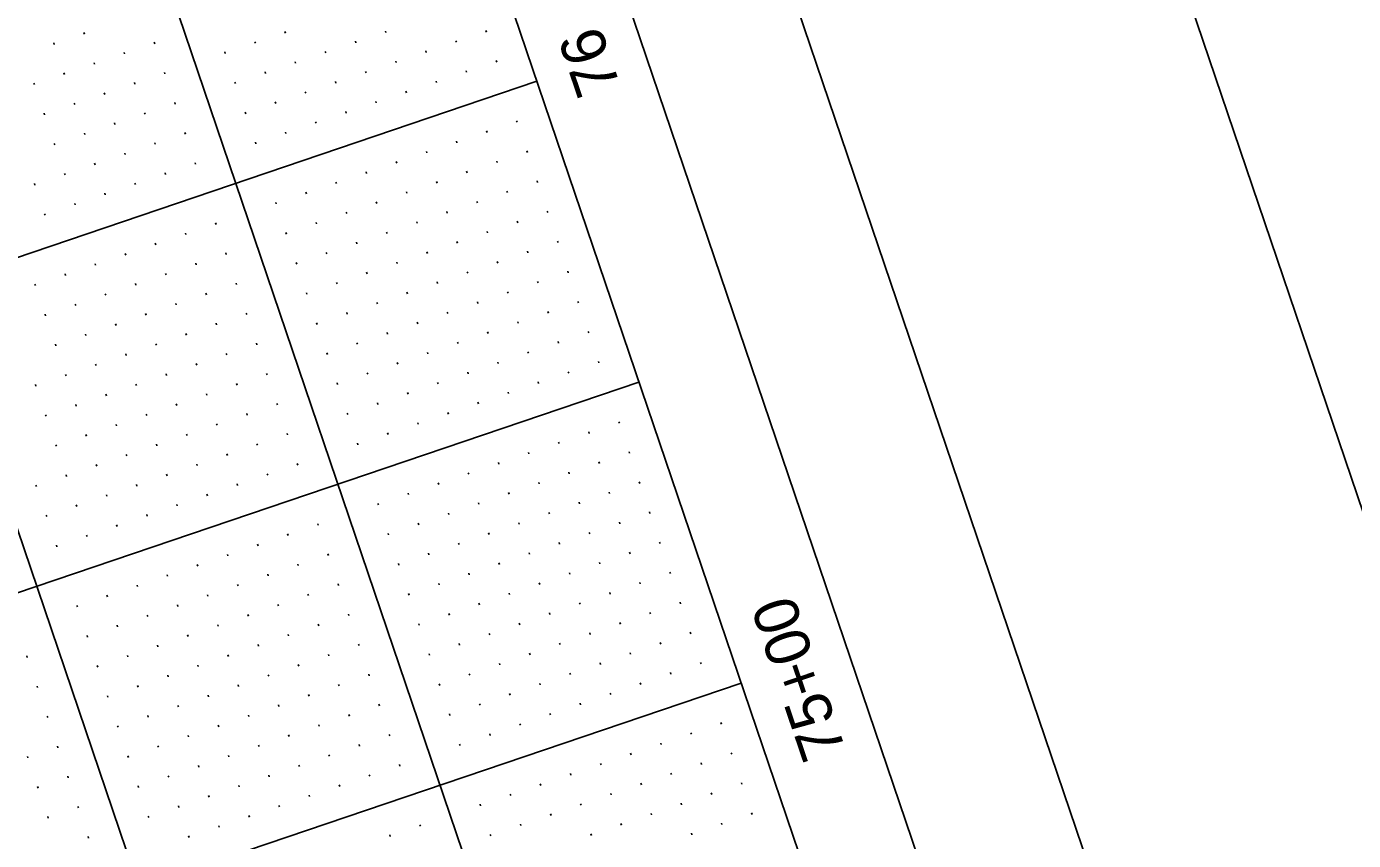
# Model space of a CAD drawing. Extents: x 2150800 to 2152547, y 141860 to 143950.
# Drawn here: x 2152172.8 to 2152381.5, y 142583.1 to 142711.2 of the extents above; entities that cross this region are included whole.
import ezdxf

# ---------------------------------------------------------------- set-up
doc = ezdxf.new("R2010")
doc.units = 0
for name, color, linetype in [('SHT_Plan_Profile_Sheet_Sta_Txt', 7, 'Continuous'), ('SHT_Plot_Shape_Full', 7, 'Continuous'), ('SHT_Plot_Shape_Half', 7, 'Continuous'), ('SHT_Profile_Grid_Major', 7, 'Continuous'), ('SHT_Profile_Grid_Minor', 7, 'Continuous'), ('SHT_Sheet_Border', 7, 'Continuous')]:
    doc.layers.add(name, color=color, linetype=linetype)

msp = doc.modelspace()

# ---------------------------------------------------------------- linework, layer by layer
at = {"layer": 'SHT_Plot_Shape_Full'}
msp.add_lwpolyline([(2151378.63, 141860.13), (2150800.36, 143564.71), (2151936.74, 143950.23), (2152515.02, 142245.65)], close=True, dxfattribs=at)
at = {"layer": 'SHT_Plot_Shape_Half'}
msp.add_lwpolyline([(2151391.39, 141950.92), (2150845.24, 143560.8), (2151886.93, 143914.19), (2152433.08, 142304.31)], close=True, dxfattribs=at)
at = {"layer": 'SHT_Profile_Grid_Major'}
for p, q in [((2152314.16, 142366.92), (2151808.17, 143858.43)), ((2152266.81, 142350.86), (2151760.82, 143842.37)), ((2152253.08, 142702.59), (2151779.81, 142542.04)), ((2152269.15, 142655.25), (2151840.6, 142509.86)), ((2152285.21, 142607.9), (2151835.31, 142455.27))]:
    msp.add_line(p, q, dxfattribs=at)
at = {"layer": 'SHT_Profile_Grid_Minor'}
for p, q in [((2152177.2, 142708.4), (2152177.11, 142708.63)), ((2152181.93, 142710), (2152181.85, 142710.24)), ((2152193.01, 142708.48), (2152192.93, 142708.72)), ((2152208.82, 142708.57), (2152208.74, 142708.8)), ((2152213.55, 142710.17), (2152213.47, 142710.41)), ((2152224.63, 142708.65), (2152224.55, 142708.89)), ((2152229.36, 142710.26), (2152229.28, 142710.49)), ((2152240.44, 142708.73), (2152240.36, 142708.97)), ((2152245.17, 142710.34), (2152245.09, 142710.58)), ((2152188.27, 142706.88), (2152188.19, 142707.11)), ((2152204.08, 142706.96), (2152204, 142707.2)), ((2152219.89, 142707.04), (2152219.81, 142707.28)), ((2152235.7, 142707.13), (2152235.62, 142707.36)), ((2152183.54, 142705.27), (2152183.46, 142705.51)), ((2152215.16, 142705.44), (2152215.08, 142705.67)), ((2152230.97, 142705.52), (2152230.89, 142705.76)), ((2152246.78, 142705.6), (2152246.7, 142705.84)), ((2152178.8, 142703.66), (2152178.72, 142703.9)), ((2152189.88, 142702.14), (2152189.8, 142702.38)), ((2152194.61, 142703.75), (2152194.53, 142703.98)), ((2152205.69, 142702.22), (2152205.61, 142702.46)), ((2152210.42, 142703.83), (2152210.34, 142704.07)), ((2152221.5, 142702.31), (2152221.42, 142702.54)), ((2152226.23, 142703.91), (2152226.15, 142704.15)), ((2152237.31, 142702.39), (2152237.23, 142702.63)), ((2152242.05, 142704), (2152241.97, 142704.24)), ((2152174.07, 142702.06), (2152173.99, 142702.29)), ((2152185.14, 142700.53), (2152185.06, 142700.77)), ((2152216.77, 142700.7), (2152216.68, 142700.94)), ((2152232.58, 142700.79), (2152232.5, 142701.02)), ((2152180.41, 142698.93), (2152180.33, 142699.16)), ((2152196.22, 142699.01), (2152196.14, 142699.25)), ((2152212.03, 142699.1), (2152211.95, 142699.33)), ((2152227.84, 142699.18), (2152227.76, 142699.42)), ((2152175.67, 142697.32), (2152175.59, 142697.56)), ((2152191.48, 142697.41), (2152191.4, 142697.64)), ((2152207.3, 142697.49), (2152207.21, 142697.73)), ((2152218.37, 142695.97), (2152218.29, 142696.2)), ((2152223.11, 142697.57), (2152223.03, 142697.81)), ((2152249.99, 142696.13), (2152249.91, 142696.37)), ((2152182.01, 142694.19), (2152181.93, 142694.43)), ((2152186.75, 142695.8), (2152186.67, 142696.04)), ((2152197.83, 142694.28), (2152197.74, 142694.51)), ((2152213.64, 142694.36), (2152213.56, 142694.6)), ((2152245.26, 142694.53), (2152245.18, 142694.77)), ((2152177.28, 142692.59), (2152177.2, 142692.82)), ((2152193.09, 142692.67), (2152193.01, 142692.91)), ((2152208.9, 142692.75), (2152208.82, 142692.99)), ((2152240.52, 142692.92), (2152240.44, 142693.16)), ((2152188.36, 142691.06), (2152188.28, 142691.3)), ((2152231.05, 142689.71), (2152230.97, 142689.95)), ((2152235.79, 142691.32), (2152235.71, 142691.55)), ((2152246.87, 142689.79), (2152246.78, 142690.03)), ((2152251.6, 142691.4), (2152251.52, 142691.64)), ((2152178.89, 142687.85), (2152178.81, 142688.09)), ((2152183.62, 142689.46), (2152183.54, 142689.69)), ((2152194.7, 142687.94), (2152194.62, 142688.17)), ((2152199.43, 142689.54), (2152199.35, 142689.78)), ((2152226.32, 142688.1), (2152226.24, 142688.34)), ((2152242.13, 142688.19), (2152242.05, 142688.42)), ((2152174.15, 142686.25), (2152174.07, 142686.48)), ((2152189.96, 142686.33), (2152189.88, 142686.57)), ((2152221.58, 142686.5), (2152221.5, 142686.73)), ((2152237.4, 142686.58), (2152237.31, 142686.82)), ((2152253.21, 142686.67), (2152253.13, 142686.9)), ((2152185.23, 142684.72), (2152185.15, 142684.96)), ((2152212.11, 142683.28), (2152212.03, 142683.52)), ((2152216.85, 142684.89), (2152216.77, 142685.13)), ((2152227.93, 142683.37), (2152227.84, 142683.61)), ((2152232.66, 142684.97), (2152232.58, 142685.21)), ((2152243.74, 142683.45), (2152243.66, 142683.69)), ((2152248.47, 142685.06), (2152248.39, 142685.3)), ((2152175.76, 142681.51), (2152175.68, 142681.75)), ((2152180.49, 142683.12), (2152180.41, 142683.35)), ((2152223.19, 142681.76), (2152223.11, 142682)), ((2152239, 142681.85), (2152238.92, 142682.08)), ((2152254.81, 142681.93), (2152254.73, 142682.17)), ((2152202.64, 142680.07), (2152202.56, 142680.31)), ((2152218.46, 142680.16), (2152218.38, 142680.39)), ((2152234.27, 142680.24), (2152234.19, 142680.48)), ((2152250.08, 142680.32), (2152250, 142680.56)), ((2152197.91, 142678.47), (2152197.83, 142678.7)), ((2152213.72, 142678.55), (2152213.64, 142678.79)), ((2152224.8, 142677.03), (2152224.72, 142677.26)), ((2152229.53, 142678.63), (2152229.45, 142678.87)), ((2152240.61, 142677.11), (2152240.53, 142677.35)), ((2152245.34, 142678.72), (2152245.26, 142678.95)), ((2152256.42, 142677.2), (2152256.34, 142677.43)), ((2152188.44, 142675.25), (2152188.36, 142675.49)), ((2152193.17, 142676.86), (2152193.09, 142677.1)), ((2152204.25, 142675.34), (2152204.17, 142675.57)), ((2152220.06, 142675.42), (2152219.98, 142675.66)), ((2152235.87, 142675.5), (2152235.79, 142675.74)), ((2152251.68, 142675.59), (2152251.6, 142675.83)), ((2152183.7, 142673.65), (2152183.62, 142673.88)), ((2152199.52, 142673.73), (2152199.44, 142673.97)), ((2152215.33, 142673.81), (2152215.25, 142674.05)), ((2152231.14, 142673.9), (2152231.06, 142674.14)), ((2152246.95, 142673.98), (2152246.87, 142674.22)), ((2152178.97, 142672.04), (2152178.89, 142672.28)), ((2152194.78, 142672.12), (2152194.7, 142672.36)), ((2152226.4, 142672.29), (2152226.32, 142672.53)), ((2152237.48, 142670.77), (2152237.4, 142671.01)), ((2152242.21, 142672.38), (2152242.13, 142672.61)), ((2152253.29, 142670.85), (2152253.21, 142671.09)), ((2152258.03, 142672.46), (2152257.94, 142672.7)), ((2152174.23, 142670.43), (2152174.15, 142670.67)), ((2152185.31, 142668.91), (2152185.23, 142669.15)), ((2152190.05, 142670.52), (2152189.97, 142670.75)), ((2152201.12, 142669), (2152201.04, 142669.23)), ((2152205.86, 142670.6), (2152205.78, 142670.84)), ((2152216.93, 142669.08), (2152216.85, 142669.32)), ((2152221.67, 142670.69), (2152221.59, 142670.92)), ((2152232.74, 142669.16), (2152232.66, 142669.4)), ((2152248.56, 142669.25), (2152248.48, 142669.48)), ((2152180.58, 142667.31), (2152180.5, 142667.54)), ((2152196.39, 142667.39), (2152196.31, 142667.63)), ((2152228.01, 142667.56), (2152227.93, 142667.79)), ((2152243.82, 142667.64), (2152243.74, 142667.88)), ((2152259.63, 142667.73), (2152259.55, 142667.96)), ((2152175.84, 142665.7), (2152175.76, 142665.94)), ((2152191.65, 142665.78), (2152191.57, 142666.02)), ((2152207.46, 142665.87), (2152207.38, 142666.1)), ((2152223.27, 142665.95), (2152223.19, 142666.19)), ((2152239.09, 142666.03), (2152239.01, 142666.27)), ((2152250.16, 142664.51), (2152250.08, 142664.75)), ((2152254.9, 142666.12), (2152254.82, 142666.36)), ((2152182.18, 142662.57), (2152182.1, 142662.81)), ((2152186.92, 142664.18), (2152186.84, 142664.41)), ((2152197.99, 142662.65), (2152197.91, 142662.89)), ((2152202.73, 142664.26), (2152202.65, 142664.5)), ((2152218.54, 142664.34), (2152218.46, 142664.58)), ((2152229.62, 142662.82), (2152229.54, 142663.06)), ((2152234.35, 142664.43), (2152234.27, 142664.67)), ((2152245.43, 142662.91), (2152245.35, 142663.14)), ((2152261.24, 142662.99), (2152261.16, 142663.23)), ((2152177.45, 142660.96), (2152177.37, 142661.2)), ((2152193.26, 142661.05), (2152193.18, 142661.28)), ((2152209.07, 142661.13), (2152208.99, 142661.37)), ((2152224.88, 142661.22), (2152224.8, 142661.45)), ((2152240.69, 142661.3), (2152240.61, 142661.54)), ((2152256.5, 142661.38), (2152256.42, 142661.62)), ((2152188.52, 142659.44), (2152188.44, 142659.68)), ((2152204.33, 142659.53), (2152204.25, 142659.76)), ((2152220.15, 142659.61), (2152220.07, 142659.85)), ((2152235.96, 142659.69), (2152235.88, 142659.93)), ((2152251.77, 142659.78), (2152251.69, 142660.01)), ((2152262.84, 142658.26), (2152262.76, 142658.49)), ((2152179.05, 142656.23), (2152178.97, 142656.47)), ((2152183.79, 142657.84), (2152183.71, 142658.07)), ((2152194.86, 142656.31), (2152194.78, 142656.55)), ((2152199.6, 142657.92), (2152199.52, 142658.16)), ((2152210.68, 142656.4), (2152210.6, 142656.63)), ((2152226.49, 142656.48), (2152226.41, 142656.72)), ((2152231.22, 142658.09), (2152231.14, 142658.32)), ((2152242.3, 142656.57), (2152242.22, 142656.8)), ((2152247.03, 142658.17), (2152246.95, 142658.41)), ((2152258.11, 142656.65), (2152258.03, 142656.89)), ((2152174.32, 142654.62), (2152174.24, 142654.86)), ((2152190.13, 142654.71), (2152190.05, 142654.94)), ((2152205.94, 142654.79), (2152205.86, 142655.03)), ((2152221.75, 142654.87), (2152221.67, 142655.11)), ((2152237.56, 142654.96), (2152237.48, 142655.2)), ((2152253.37, 142655.04), (2152253.29, 142655.28)), ((2152185.39, 142653.1), (2152185.31, 142653.34)), ((2152201.21, 142653.18), (2152201.13, 142653.42)), ((2152232.83, 142653.35), (2152232.75, 142653.59)), ((2152248.64, 142653.44), (2152248.56, 142653.67)), ((2152180.66, 142651.49), (2152180.58, 142651.73)), ((2152191.74, 142649.97), (2152191.66, 142650.21)), ((2152196.47, 142651.58), (2152196.39, 142651.81)), ((2152207.55, 142650.06), (2152207.47, 142650.29)), ((2152212.28, 142651.66), (2152212.2, 142651.9)), ((2152223.36, 142650.14), (2152223.28, 142650.38)), ((2152228.09, 142651.75), (2152228.01, 142651.98)), ((2152239.17, 142650.22), (2152239.09, 142650.46)), ((2152243.9, 142651.83), (2152243.82, 142652.07)), ((2152175.92, 142649.89), (2152175.84, 142650.12)), ((2152187, 142648.37), (2152186.92, 142648.6)), ((2152202.81, 142648.45), (2152202.73, 142648.69)), ((2152234.43, 142648.62), (2152234.35, 142648.85)), ((2152266.06, 142648.79), (2152265.98, 142649.02)), ((2152182.27, 142646.76), (2152182.19, 142647)), ((2152198.08, 142646.84), (2152198, 142647.08)), ((2152213.89, 142646.93), (2152213.81, 142647.16)), ((2152229.7, 142647.01), (2152229.62, 142647.25)), ((2152261.32, 142647.18), (2152261.24, 142647.42)), ((2152177.53, 142645.15), (2152177.45, 142645.39)), ((2152193.34, 142645.24), (2152193.26, 142645.47)), ((2152204.42, 142643.71), (2152204.34, 142643.95)), ((2152209.15, 142645.32), (2152209.07, 142645.56)), ((2152224.96, 142645.4), (2152224.88, 142645.64)), ((2152251.85, 142643.97), (2152251.77, 142644.2)), ((2152256.59, 142645.57), (2152256.51, 142645.81)), ((2152267.66, 142644.05), (2152267.58, 142644.29)), ((2152183.87, 142642.02), (2152183.79, 142642.26)), ((2152188.61, 142643.63), (2152188.53, 142643.87)), ((2152199.68, 142642.11), (2152199.6, 142642.34)), ((2152215.49, 142642.19), (2152215.41, 142642.43)), ((2152247.12, 142642.36), (2152247.04, 142642.6)), ((2152262.93, 142642.44), (2152262.85, 142642.68)), ((2152179.14, 142640.42), (2152179.06, 142640.65)), ((2152194.95, 142640.5), (2152194.87, 142640.74)), ((2152210.76, 142640.59), (2152210.68, 142640.82)), ((2152242.38, 142640.75), (2152242.3, 142640.99)), ((2152258.19, 142640.84), (2152258.11, 142641.07)), ((2152174.4, 142638.81), (2152174.32, 142639.05)), ((2152190.21, 142638.9), (2152190.13, 142639.13)), ((2152206.02, 142638.98), (2152205.94, 142639.22)), ((2152232.91, 142637.54), (2152232.83, 142637.78)), ((2152237.65, 142639.15), (2152237.57, 142639.38)), ((2152248.72, 142637.63), (2152248.64, 142637.86)), ((2152253.46, 142639.23), (2152253.38, 142639.47)), ((2152264.53, 142637.71), (2152264.45, 142637.95)), ((2152269.27, 142639.32), (2152269.19, 142639.55)), ((2152180.74, 142635.68), (2152180.66, 142635.92)), ((2152185.48, 142637.29), (2152185.4, 142637.53)), ((2152196.55, 142635.77), (2152196.47, 142636)), ((2152201.29, 142637.37), (2152201.21, 142637.61)), ((2152228.18, 142635.93), (2152228.1, 142636.17)), ((2152243.99, 142636.02), (2152243.91, 142636.26)), ((2152259.8, 142636.1), (2152259.72, 142636.34)), ((2152176.01, 142634.08), (2152175.93, 142634.31)), ((2152191.82, 142634.16), (2152191.74, 142634.4)), ((2152239.25, 142634.41), (2152239.17, 142634.65)), ((2152255.06, 142634.5), (2152254.98, 142634.73)), ((2152270.88, 142634.58), (2152270.8, 142634.82)), ((2152187.09, 142632.55), (2152187, 142632.79)), ((2152218.71, 142632.72), (2152218.63, 142632.96)), ((2152229.78, 142631.2), (2152229.7, 142631.44)), ((2152234.52, 142632.81), (2152234.44, 142633.04)), ((2152245.59, 142631.28), (2152245.51, 142631.52)), ((2152250.33, 142632.89), (2152250.25, 142633.13)), ((2152261.41, 142631.37), (2152261.33, 142631.6)), ((2152266.14, 142632.97), (2152266.06, 142633.21)), ((2152177.62, 142629.34), (2152177.53, 142629.58)), ((2152182.35, 142630.95), (2152182.27, 142631.18)), ((2152209.24, 142629.51), (2152209.16, 142629.75)), ((2152213.97, 142631.12), (2152213.89, 142631.35)), ((2152240.86, 142629.68), (2152240.78, 142629.91)), ((2152256.67, 142629.76), (2152256.59, 142630)), ((2152272.48, 142629.85), (2152272.4, 142630.08)), ((2152204.5, 142627.9), (2152204.42, 142628.14)), ((2152220.31, 142627.99), (2152220.23, 142628.22)), ((2152236.12, 142628.07), (2152236.04, 142628.31)), ((2152251.94, 142628.16), (2152251.86, 142628.39)), ((2152267.75, 142628.24), (2152267.67, 142628.48)), ((2152199.77, 142626.3), (2152199.69, 142626.53)), ((2152215.58, 142626.38), (2152215.5, 142626.62)), ((2152231.39, 142626.47), (2152231.31, 142626.7)), ((2152242.47, 142624.94), (2152242.39, 142625.18)), ((2152247.2, 142626.55), (2152247.12, 142626.79)), ((2152258.28, 142625.03), (2152258.2, 142625.26)), ((2152263.01, 142626.63), (2152262.93, 142626.87)), ((2152274.09, 142625.11), (2152274.01, 142625.35)), ((2152190.3, 142623.08), (2152190.22, 142623.32)), ((2152195.03, 142624.69), (2152194.95, 142624.93)), ((2152206.11, 142623.17), (2152206.03, 142623.41)), ((2152210.84, 142624.77), (2152210.76, 142625.01)), ((2152221.92, 142623.25), (2152221.84, 142623.49)), ((2152237.73, 142623.34), (2152237.65, 142623.57)), ((2152253.54, 142623.42), (2152253.46, 142623.66)), ((2152269.35, 142623.5), (2152269.27, 142623.74)), ((2152185.56, 142621.48), (2152185.48, 142621.71)), ((2152201.37, 142621.56), (2152201.29, 142621.8)), ((2152217.19, 142621.65), (2152217.1, 142621.88)), ((2152233, 142621.73), (2152232.92, 142621.97)), ((2152248.81, 142621.81), (2152248.73, 142622.05)), ((2152264.62, 142621.9), (2152264.54, 142622.13)), ((2152180.83, 142619.87), (2152180.75, 142620.11)), ((2152196.64, 142619.96), (2152196.56, 142620.19)), ((2152212.45, 142620.04), (2152212.37, 142620.28)), ((2152239.34, 142618.6), (2152239.26, 142618.84)), ((2152244.07, 142620.21), (2152243.99, 142620.44)), ((2152255.15, 142618.69), (2152255.07, 142618.92)), ((2152259.88, 142620.29), (2152259.8, 142620.53)), ((2152270.96, 142618.77), (2152270.88, 142619.01)), ((2152275.69, 142620.38), (2152275.61, 142620.61)), ((2152187.17, 142616.74), (2152187.09, 142616.98)), ((2152191.9, 142618.35), (2152191.82, 142618.59)), ((2152202.98, 142616.83), (2152202.9, 142617.06)), ((2152207.72, 142618.43), (2152207.63, 142618.67)), ((2152218.79, 142616.91), (2152218.71, 142617.15)), ((2152223.53, 142618.52), (2152223.45, 142618.75)), ((2152234.6, 142617), (2152234.52, 142617.23)), ((2152250.41, 142617.08), (2152250.33, 142617.32)), ((2152266.22, 142617.16), (2152266.14, 142617.4)), ((2152182.43, 142615.14), (2152182.35, 142615.37)), ((2152198.25, 142615.22), (2152198.16, 142615.46)), ((2152214.06, 142615.3), (2152213.98, 142615.54)), ((2152245.68, 142615.47), (2152245.6, 142615.71)), ((2152261.49, 142615.56), (2152261.41, 142615.79)), ((2152277.3, 142615.64), (2152277.22, 142615.88)), ((2152193.51, 142613.61), (2152193.43, 142613.85)), ((2152209.32, 142613.7), (2152209.24, 142613.94)), ((2152225.13, 142613.78), (2152225.05, 142614.02)), ((2152240.94, 142613.87), (2152240.86, 142614.1)), ((2152252.02, 142612.34), (2152251.94, 142612.58)), ((2152256.75, 142613.95), (2152256.67, 142614.19)), ((2152267.83, 142612.43), (2152267.75, 142612.66)), ((2152272.57, 142614.03), (2152272.49, 142614.27)), ((2152172.96, 142611.92), (2152172.88, 142612.16)), ((2152184.04, 142610.4), (2152183.96, 142610.64)), ((2152188.78, 142612.01), (2152188.7, 142612.24)), ((2152199.85, 142610.49), (2152199.77, 142610.72)), ((2152204.59, 142612.09), (2152204.51, 142612.33)), ((2152215.66, 142610.57), (2152215.58, 142610.81)), ((2152220.4, 142612.18), (2152220.32, 142612.41)), ((2152236.21, 142612.26), (2152236.13, 142612.5)), ((2152247.29, 142610.74), (2152247.2, 142610.97)), ((2152263.1, 142610.82), (2152263.02, 142611.06)), ((2152278.91, 142610.91), (2152278.83, 142611.14)), ((2152195.12, 142608.88), (2152195.04, 142609.12)), ((2152210.93, 142608.96), (2152210.85, 142609.2)), ((2152226.74, 142609.05), (2152226.66, 142609.28)), ((2152242.55, 142609.13), (2152242.47, 142609.37)), ((2152258.36, 142609.22), (2152258.28, 142609.45)), ((2152274.17, 142609.3), (2152274.09, 142609.54)), ((2152174.57, 142607.19), (2152174.49, 142607.43)), ((2152190.38, 142607.27), (2152190.3, 142607.51)), ((2152206.19, 142607.36), (2152206.11, 142607.59)), ((2152222, 142607.44), (2152221.92, 142607.68)), ((2152237.82, 142607.53), (2152237.73, 142607.76)), ((2152253.63, 142607.61), (2152253.55, 142607.85)), ((2152264.7, 142606.09), (2152264.62, 142606.32)), ((2152269.44, 142607.69), (2152269.36, 142607.93)), ((2152185.65, 142605.67), (2152185.57, 142605.9)), ((2152196.72, 142604.14), (2152196.64, 142604.38)), ((2152201.46, 142605.75), (2152201.38, 142605.99)), ((2152212.53, 142604.23), (2152212.45, 142604.47)), ((2152217.27, 142605.83), (2152217.19, 142606.07)), ((2152228.35, 142604.31), (2152228.26, 142604.55)), ((2152244.16, 142604.4), (2152244.08, 142604.63)), ((2152248.89, 142606), (2152248.81, 142606.24)), ((2152259.97, 142604.48), (2152259.89, 142604.72)), ((2152176.18, 142602.45), (2152176.1, 142602.69)), ((2152191.99, 142602.54), (2152191.91, 142602.78)), ((2152207.8, 142602.62), (2152207.72, 142602.86)), ((2152223.61, 142602.71), (2152223.53, 142602.94)), ((2152239.42, 142602.79), (2152239.34, 142603.03)), ((2152255.23, 142602.87), (2152255.15, 142603.11)), ((2152187.25, 142600.93), (2152187.17, 142601.17)), ((2152203.06, 142601.02), (2152202.98, 142601.25)), ((2152218.88, 142601.1), (2152218.8, 142601.34)), ((2152250.5, 142601.27), (2152250.42, 142601.5)), ((2152277.39, 142599.83), (2152277.3, 142600.07)), ((2152282.12, 142601.44), (2152282.04, 142601.67)), ((2152193.59, 142597.8), (2152193.51, 142598.04)), ((2152198.33, 142599.41), (2152198.25, 142599.65)), ((2152209.41, 142597.89), (2152209.33, 142598.12)), ((2152214.14, 142599.49), (2152214.06, 142599.73)), ((2152225.22, 142597.97), (2152225.14, 142598.21)), ((2152229.95, 142599.58), (2152229.87, 142599.81)), ((2152241.03, 142598.06), (2152240.95, 142598.29)), ((2152245.76, 142599.66), (2152245.68, 142599.9)), ((2152272.65, 142598.22), (2152272.57, 142598.46)), ((2152173.05, 142596.11), (2152172.97, 142596.35)), ((2152177.78, 142597.72), (2152177.7, 142597.96)), ((2152188.86, 142596.2), (2152188.78, 142596.43)), ((2152204.67, 142596.28), (2152204.59, 142596.52)), ((2152220.48, 142596.37), (2152220.4, 142596.6)), ((2152267.92, 142596.62), (2152267.83, 142596.85)), ((2152283.73, 142596.7), (2152283.65, 142596.94)), ((2152199.94, 142594.67), (2152199.86, 142594.91)), ((2152215.75, 142594.76), (2152215.67, 142595)), ((2152231.56, 142594.84), (2152231.48, 142595.08)), ((2152263.18, 142595.01), (2152263.1, 142595.25)), ((2152278.99, 142595.09), (2152278.91, 142595.33)), ((2152179.39, 142592.98), (2152179.31, 142593.22)), ((2152195.2, 142593.07), (2152195.12, 142593.31)), ((2152206.28, 142591.55), (2152206.2, 142591.78)), ((2152211.01, 142593.15), (2152210.93, 142593.39)), ((2152222.09, 142591.63), (2152222.01, 142591.87)), ((2152226.82, 142593.24), (2152226.74, 142593.47)), ((2152253.71, 142591.8), (2152253.63, 142592.03)), ((2152258.45, 142593.4), (2152258.37, 142593.64)), ((2152269.52, 142591.88), (2152269.44, 142592.12)), ((2152274.26, 142593.49), (2152274.18, 142593.73)), ((2152285.33, 142591.97), (2152285.25, 142592.2)), ((2152174.65, 142591.38), (2152174.57, 142591.61)), ((2152190.47, 142591.46), (2152190.39, 142591.7)), ((2152201.54, 142589.94), (2152201.46, 142590.18)), ((2152217.35, 142590.02), (2152217.27, 142590.26)), ((2152248.98, 142590.19), (2152248.9, 142590.43)), ((2152264.79, 142590.28), (2152264.71, 142590.51)), ((2152280.6, 142590.36), (2152280.52, 142590.6)), ((2152181, 142588.25), (2152180.92, 142588.49)), ((2152196.81, 142588.33), (2152196.73, 142588.57)), ((2152212.62, 142588.42), (2152212.54, 142588.65)), ((2152244.24, 142588.59), (2152244.16, 142588.82)), ((2152260.05, 142588.67), (2152259.97, 142588.91)), ((2152275.86, 142588.75), (2152275.78, 142588.99)), ((2152176.26, 142586.64), (2152176.18, 142586.88)), ((2152192.07, 142586.73), (2152191.99, 142586.96)), ((2152207.88, 142586.81), (2152207.8, 142587.05)), ((2152234.77, 142585.37), (2152234.69, 142585.61)), ((2152250.58, 142585.46), (2152250.5, 142585.69)), ((2152255.32, 142587.06), (2152255.24, 142587.3)), ((2152266.39, 142585.54), (2152266.31, 142585.78)), ((2152271.13, 142587.15), (2152271.05, 142587.38)), ((2152282.2, 142585.62), (2152282.12, 142585.86)), ((2152286.94, 142587.23), (2152286.86, 142587.47)), ((2152182.6, 142583.51), (2152182.52, 142583.75)), ((2152198.41, 142583.6), (2152198.33, 142583.84)), ((2152203.15, 142585.2), (2152203.07, 142585.44)), ((2152230.04, 142583.77), (2152229.96, 142584)), ((2152245.85, 142583.85), (2152245.77, 142584.09)), ((2152261.66, 142583.93), (2152261.58, 142584.17)), ((2152277.47, 142584.02), (2152277.39, 142584.26))]:
    msp.add_line(p, q, dxfattribs=at)
at = {"layer": 'SHT_Sheet_Border'}
msp.add_line((2152361.51, 142382.99), (2151939.85, 143625.91), dxfattribs=at)
msp.add_lwpolyline([(2151383.74, 142051.28), (2150877.75, 143542.79), (2151872.09, 143880.12), (2152378.08, 142388.61)], close=True, dxfattribs=at)

# ---------------------------------------------------------------- texts
at = {"layer": 'SHT_Plan_Profile_Sheet_Sta_Txt'}
for s, p in [('76', (2152266.32, 142701.71)), ('75+00', (2152301.77, 142597.19))]:
    msp.add_text(s, height=7, rotation=108.7393, dxfattribs=at).set_placement(p)

doc.saveas('drawing.dxf')
